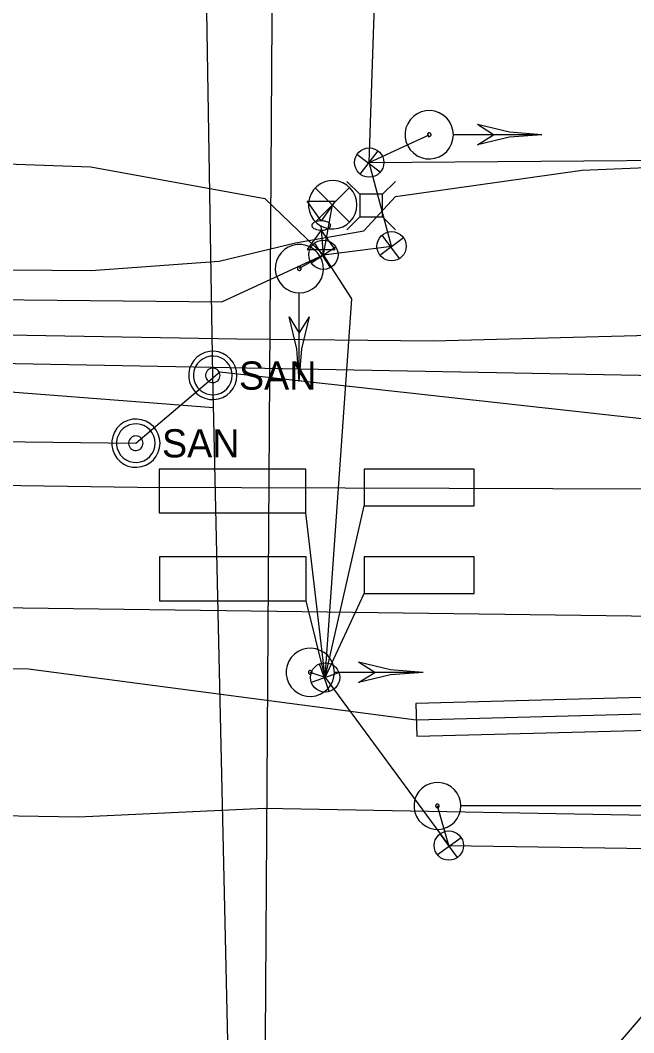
# Model space of a CAD drawing. Extents: x 600849 to 606371, y 330010 to 403088.
# Drawn here: x 604965.8 to 605049.6, y 332631.5 to 332769.8 of the extents above; entities that cross this region are included whole.
import ezdxf

# ---------------------------------------------------------------- set-up
doc = ezdxf.new("R2010")
doc.units = 0
for name, color, linetype in [('E_LTG_CID', 7, 'Continuous'), ('E_SIG', 7, 'Continuous'), ('E_SIG_Conduit', 7, 'Continuous'), ('E_UTL_AG', 7, 'Continuous'), ('E_UTL_AG_Bold', 7, 'Continuous'), ('E_UTL_E_UG', 7, 'Continuous'), ('E_UTL_G_UG', 7, 'Continuous'), ('E_UTL_Loop_UG', 7, 'Continuous'), ('E_UTL_SAN', 7, 'Continuous'), ('E_UTL_SAN_UG', 7, 'Continuous'), ('E_UTL_SAN_UG_MMSD', 7, 'Continuous'), ('E_UTL_T_UG', 7, 'Continuous'), ('E_UTL_TV_UG', 7, 'Continuous'), ('E_UTL_W_UG', 7, 'Continuous')]:
    doc.layers.add(name, color=color, linetype=linetype)

# ---------------------------------------------------------------- blocks, each defined once
blk = doc.blocks.new('_U300')
at = {"layer": 'E_SIG'}
for p, q in [((0, 6.1), (0, -6.1)), ((-6.09, 0.4), (6.1, 0.4))]:
    blk.add_line(p, q, dxfattribs=at)
blk.add_circle((0, 0.01), 6.1, dxfattribs=at)
blk = doc.blocks.new('_U305')
at = {"layer": 'E_SIG'}
for p, q in [((0, 6.1), (0, -6.1)), ((-6.09, 0.4), (6.1, 0.4))]:
    blk.add_line(p, q, dxfattribs=at)
blk.add_circle((0, 0.01), 6.1, dxfattribs=at)
blk = doc.blocks.new('_U306')
at = {"layer": 'E_SIG'}
for p, q in [((0, 6.1), (0, -6.1)), ((-6.09, 0.4), (6.1, 0.4))]:
    blk.add_line(p, q, dxfattribs=at)
blk.add_circle((0, 0.01), 6.1, dxfattribs=at)
blk = doc.blocks.new('_U307')
at = {"layer": 'E_SIG'}
for p, q in [((0, 6.1), (0, -6.1)), ((-6.09, 0.4), (6.1, 0.4))]:
    blk.add_line(p, q, dxfattribs=at)
blk.add_circle((0, 0.01), 6.1, dxfattribs=at)
blk = doc.blocks.new('_U308')
at = {"layer": 'E_SIG'}
for p, q in [((0, 6.1), (0, -6.1)), ((-6.09, 0.4), (6.1, 0.4))]:
    blk.add_line(p, q, dxfattribs=at)
blk.add_circle((0, 0.01), 6.1, dxfattribs=at)

msp = doc.modelspace()

# ---------------------------------------------------------------- linework, layer by layer
at = {"layer": 'E_LTG_CID'}
msp.add_lwpolyline([(604931.85, 331581.07), (604937.27, 331603.67), (604947.8, 331650.94), (604952, 331678.28), (604955.83, 331701.76), (604989.48, 331966.47), (604996.27, 332242.26), (604998.49, 332512.59), (605000.29, 332783.81), (605002.15, 332931.75), (605000.64, 332964.83), (605000.69, 332966.2), (605002.17, 333011.44), (605003.78, 333073.37), (605005.15, 333128.46), (605004.43, 333142.5)], dxfattribs=at)
at = {"layer": 'E_SIG'}
for points in [[(605024.93, 332754.16), (605024.87, 332754.79), (605024.69, 332755.39), (605024.41, 332755.95), (605024.02, 332756.44), (605023.54, 332756.85), (605023, 332757.16), (605022.41, 332757.37), (605021.79, 332757.46), (605021.16, 332757.43), (605020.55, 332757.28), (605019.98, 332757.02), (605019.47, 332756.65), (605019.04, 332756.2), (605018.7, 332755.67), (605018.46, 332755.09), (605018.35, 332754.47), (605018.35, 332753.85), (605018.46, 332753.23), (605018.7, 332752.65), (605019.04, 332752.12), (605019.47, 332751.67), (605019.98, 332751.3), (605020.55, 332751.04), (605021.16, 332750.89), (605021.79, 332750.86), (605022.41, 332750.95), (605023, 332751.16), (605023.54, 332751.47), (605024.02, 332751.88), (605024.41, 332752.38), (605024.69, 332752.93), (605024.87, 332753.54), (605024.93, 332754.16)], [(605037.03, 332754.16), (605032.58, 332754.51), (605028.23, 332755.54)], [(605030.43, 332754.16), (605028.23, 332755.54)], [(605021.88, 332754.16), (605021.88, 332754.21), (605021.87, 332754.25), (605021.84, 332754.3), (605021.81, 332754.34), (605021.78, 332754.37), (605021.74, 332754.39), (605021.69, 332754.41), (605021.64, 332754.41), (605021.59, 332754.41), (605021.55, 332754.4), (605021.5, 332754.38), (605021.47, 332754.35), (605021.43, 332754.32), (605021.41, 332754.28), (605021.39, 332754.23), (605021.38, 332754.18), (605021.38, 332754.14), (605021.39, 332754.09), (605021.41, 332754.05), (605021.43, 332754), (605021.47, 332753.97), (605021.5, 332753.94), (605021.55, 332753.92), (605021.59, 332753.91), (605021.64, 332753.91), (605021.69, 332753.92), (605021.74, 332753.93), (605021.78, 332753.96), (605021.81, 332753.99), (605021.84, 332754.02), (605021.87, 332754.07), (605021.88, 332754.11), (605021.88, 332754.16)], [(605037.03, 332754.16), (605024.99, 332754.16)], [(605037.03, 332754.16), (605032.58, 332753.82), (605028.23, 332752.79)], [(605028.23, 332752.79), (605030.43, 332754.16)], [(605011.75, 332744.6), (605011.7, 332745.22), (605011.52, 332745.82), (605011.23, 332746.38), (605010.84, 332746.87), (605010.37, 332747.28), (605009.83, 332747.6), (605009.23, 332747.8), (605008.61, 332747.89), (605007.99, 332747.86), (605007.38, 332747.72), (605006.8, 332747.45), (605006.29, 332747.09), (605005.86, 332746.64), (605005.52, 332746.11), (605005.29, 332745.53), (605005.17, 332744.91), (605005.17, 332744.28), (605005.29, 332743.67), (605005.52, 332743.08), (605005.86, 332742.56), (605006.29, 332742.1), (605006.8, 332741.74), (605007.38, 332741.48), (605007.99, 332741.33), (605008.61, 332741.3), (605009.23, 332741.39), (605009.83, 332741.59), (605010.37, 332741.91), (605010.84, 332742.32), (605011.23, 332742.81), (605011.52, 332743.37), (605011.7, 332743.97), (605011.75, 332744.6)], [(605010.72, 332746.93), (605006.11, 332742.27)], [(605006.11, 332746.88), (605010.76, 332742.23)], [(605003.9, 332732.58), (605004.53, 332732.64), (605005.13, 332732.82), (605005.69, 332733.1), (605006.18, 332733.49), (605006.59, 332733.97), (605006.91, 332734.51), (605007.11, 332735.1), (605007.2, 332735.72), (605007.17, 332736.35), (605007.02, 332736.96), (605006.76, 332737.53), (605006.4, 332738.04), (605005.94, 332738.47), (605005.42, 332738.81), (605004.83, 332739.05), (605004.22, 332739.17), (605003.59, 332739.17), (605002.97, 332739.05), (605002.39, 332738.81), (605001.86, 332738.47), (605001.41, 332738.04), (605001.05, 332737.53), (605000.78, 332736.96), (605000.64, 332736.35), (605000.61, 332735.72), (605000.7, 332735.1), (605000.9, 332734.51), (605001.22, 332733.97), (605001.63, 332733.49), (605002.12, 332733.1), (605002.68, 332732.82), (605003.28, 332732.64), (605003.9, 332732.58)], [(605003.9, 332735.63), (605003.95, 332735.63), (605004, 332735.65), (605004.04, 332735.67), (605004.08, 332735.7), (605004.11, 332735.73), (605004.13, 332735.78), (605004.15, 332735.82), (605004.16, 332735.87), (605004.15, 332735.92), (605004.14, 332735.96), (605004.12, 332736.01), (605004.09, 332736.05), (605004.06, 332736.08), (605004.02, 332736.11), (605003.97, 332736.12), (605003.93, 332736.13), (605003.88, 332736.13), (605003.83, 332736.12), (605003.79, 332736.11), (605003.75, 332736.08), (605003.71, 332736.05), (605003.68, 332736.01), (605003.66, 332735.96), (605003.65, 332735.92), (605003.65, 332735.87), (605003.66, 332735.82), (605003.67, 332735.78), (605003.7, 332735.73), (605003.73, 332735.7), (605003.77, 332735.67), (605003.81, 332735.65), (605003.86, 332735.63), (605003.9, 332735.63)], [(605003.9, 332720.48), (605003.9, 332732.52)], [(605003.9, 332720.48), (605003.56, 332724.93), (605002.53, 332729.28)], [(605002.53, 332729.28), (605003.9, 332727.08)], [(605003.9, 332720.48), (605004.25, 332724.93), (605005.28, 332729.28)], [(605003.9, 332727.08), (605005.28, 332729.28)], [(605008.69, 332680.75), (605008.63, 332681.38), (605008.46, 332681.98), (605008.17, 332682.54), (605007.78, 332683.03), (605007.31, 332683.44), (605006.76, 332683.75), (605006.17, 332683.96), (605005.55, 332684.05), (605004.92, 332684.02), (605004.31, 332683.87), (605003.74, 332683.61), (605003.23, 332683.25), (605002.8, 332682.79), (605002.46, 332682.27), (605002.23, 332681.68), (605002.11, 332681.07), (605002.11, 332680.44), (605002.23, 332679.82), (605002.46, 332679.24), (605002.8, 332678.71), (605003.23, 332678.26), (605003.74, 332677.9), (605004.31, 332677.63), (605004.92, 332677.49), (605005.55, 332677.46), (605006.17, 332677.55), (605006.76, 332677.75), (605007.31, 332678.07), (605007.78, 332678.48), (605008.17, 332678.97), (605008.46, 332679.53), (605008.63, 332680.13), (605008.69, 332680.75)], [(605020.79, 332680.75), (605016.34, 332681.1), (605011.99, 332682.13)], [(605014.19, 332680.75), (605011.99, 332682.13)], [(605005.65, 332680.75), (605005.64, 332680.8), (605005.63, 332680.85), (605005.61, 332680.89), (605005.58, 332680.93), (605005.54, 332680.96), (605005.5, 332680.98), (605005.45, 332681), (605005.41, 332681.01), (605005.36, 332681), (605005.31, 332680.99), (605005.27, 332680.97), (605005.23, 332680.94), (605005.2, 332680.91), (605005.17, 332680.87), (605005.15, 332680.82), (605005.14, 332680.78), (605005.14, 332680.73), (605005.15, 332680.68), (605005.17, 332680.64), (605005.2, 332680.6), (605005.23, 332680.56), (605005.27, 332680.53), (605005.31, 332680.51), (605005.36, 332680.5), (605005.41, 332680.5), (605005.45, 332680.51), (605005.5, 332680.52), (605005.54, 332680.55), (605005.58, 332680.58), (605005.61, 332680.62), (605005.63, 332680.66), (605005.64, 332680.71), (605005.65, 332680.75)], [(605007.43, 332680.06), (605005.39, 332680.75)], [(605020.79, 332680.75), (605008.75, 332680.75)], [(605020.79, 332680.75), (605016.34, 332680.41), (605011.99, 332679.38)], [(605011.99, 332679.38), (605014.19, 332680.75)], [(605025.96, 332662.51), (605025.9, 332663.12), (605025.73, 332663.7), (605025.45, 332664.25), (605025.08, 332664.72), (605024.62, 332665.12), (605024.09, 332665.43), (605023.51, 332665.63), (605022.91, 332665.71), (605022.3, 332665.68), (605021.71, 332665.54), (605021.16, 332665.29), (605020.66, 332664.93), (605020.24, 332664.49), (605019.91, 332663.98), (605019.69, 332663.42), (605019.57, 332662.82), (605019.57, 332662.21), (605019.69, 332661.61), (605019.91, 332661.05), (605020.24, 332660.53), (605020.66, 332660.09), (605021.16, 332659.74), (605021.71, 332659.49), (605022.3, 332659.34), (605022.91, 332659.31), (605023.51, 332659.4), (605024.09, 332659.6), (605024.62, 332659.91), (605025.08, 332660.3), (605025.45, 332660.78), (605025.73, 332661.32), (605025.9, 332661.91), (605025.96, 332662.51)], [(605023, 332662.51), (605023, 332662.56), (605022.99, 332662.61), (605022.96, 332662.65), (605022.94, 332662.68), (605022.9, 332662.71), (605022.86, 332662.74), (605022.82, 332662.75), (605022.77, 332662.76), (605022.72, 332662.76), (605022.68, 332662.75), (605022.64, 332662.73), (605022.6, 332662.7), (605022.57, 332662.67), (605022.54, 332662.63), (605022.52, 332662.58), (605022.51, 332662.54), (605022.51, 332662.49), (605022.52, 332662.45), (605022.54, 332662.4), (605022.57, 332662.36), (605022.6, 332662.33), (605022.64, 332662.3), (605022.68, 332662.28), (605022.72, 332662.27), (605022.77, 332662.27), (605022.82, 332662.28), (605022.86, 332662.29), (605022.9, 332662.31), (605022.94, 332662.35), (605022.96, 332662.38), (605022.99, 332662.42), (605023, 332662.47), (605023, 332662.51)], [(605024.31, 332657.1), (605022.76, 332662.51)], [(605052.65, 332662.52), (605026.01, 332662.52)], [(605045.18, 332662.52), (605045.18, 332662.52)]]:
    msp.add_lwpolyline(points, dxfattribs=at)
at = {"layer": 'E_SIG_Conduit'}
msp.add_line((605007.19, 332737.78), (605003.9, 332735.88), dxfattribs=at)
for points in [[(605013.44, 332750.37), (605018.8, 332909.2), (605014.77, 333003.78)], [(605013.44, 332750.37), (605021.63, 332754.16)], [(605007.43, 332680.06), (605011.08, 332731.74), (605007.19, 332737.78), (605016.5, 332738.93), (605013.44, 332750.37), (605060.3, 332750.72), (605093.78, 332739.36)], [(605007.19, 332737.78), (605008.45, 332744.6)], [(605007.19, 332737.78), (605006.89, 332741.77)], [(604921.39, 332732.09), (604993.31, 332731.34), (605007.19, 332737.78)], [(605007.43, 332680.06), (605024.31, 332657.1), (605054.73, 332656.67), (605096.42, 332660.59), (605109.2, 332679.54), (605110.22, 332731.89)]]:
    msp.add_lwpolyline(points, dxfattribs=at)
at = {"layer": 'E_UTL_AG'}
for points in [[(605004.99, 332745.07), (605008.8, 332745.07)], [(605006.89, 332742.4), (605004.99, 332745.07)], [(605008.8, 332745.07), (605006.89, 332742.4)], [(605008.16, 332741.77), (605008.14, 332741.89), (605008.07, 332742), (605007.96, 332742.11), (605007.81, 332742.21), (605007.63, 332742.28), (605007.42, 332742.35), (605007.19, 332742.38), (605006.95, 332742.4), (605006.71, 332742.4), (605006.48, 332742.37), (605006.26, 332742.32), (605006.06, 332742.25), (605005.89, 332742.16), (605005.76, 332742.06), (605005.67, 332741.95), (605005.63, 332741.83), (605005.63, 332741.71), (605005.67, 332741.59), (605005.76, 332741.48), (605005.89, 332741.37), (605006.06, 332741.29), (605006.26, 332741.22), (605006.48, 332741.17), (605006.71, 332741.14), (605006.95, 332741.13), (605007.19, 332741.15), (605007.42, 332741.19), (605007.63, 332741.25), (605007.81, 332741.33), (605007.96, 332741.42), (605008.07, 332741.53), (605008.14, 332741.65), (605008.16, 332741.77)], [(605006.89, 332741.13), (605004.99, 332738.47)], [(605008.8, 332738.47), (605006.89, 332741.13)], [(605004.99, 332738.47), (605008.8, 332738.47)]]:
    msp.add_lwpolyline(points, dxfattribs=at)
at = {"layer": 'E_UTL_AG_Bold'}
for points in [[(605012.16, 332746.04), (605010.41, 332747.79)], [(605015.26, 332746.04), (605017.01, 332747.79)], [(605015.26, 332746.04), (605012.16, 332746.04)], [(605012.16, 332746.04), (605012.16, 332742.94)], [(605015.26, 332742.94), (605015.26, 332746.04)], [(605012.16, 332742.94), (605010.41, 332741.19)], [(605012.16, 332742.94), (605015.26, 332742.94)], [(605015.26, 332742.94), (605017.01, 332741.19)]]:
    msp.add_lwpolyline(points, dxfattribs=at)
at = {"layer": 'E_UTL_E_UG'}
msp.add_line((604415.87, 332733.34), (605162.93, 332719.18), dxfattribs=at)
msp.add_lwpolyline([(604883.85, 332749.45), (604890.54, 332751.38), (604904.52, 332751.83), (604930.8, 332751.36), (604975.43, 332749.76), (604999.19, 332745.44), (605007.19, 332737.78)], dxfattribs=at)
at = {"layer": 'E_UTL_G_UG'}
msp.add_line((604453.34, 332696.36), (605095.21, 332687.86), dxfattribs=at)
msp.add_line((604453.34, 332696.36), (605095.21, 332687.86), dxfattribs=at)
msp.add_lwpolyline([(605000.09, 332338.31), (605000.11, 332381.53), (605000.58, 332421.33), (605000.12, 332494.14), (605001.25, 332517.82), (605001.72, 332543.05), (605001.99, 332582.9), (605009.14, 332588.51), (605017.08, 332595.02), (605025.17, 332603.98), (605053.2, 332636.73), (605068.82, 332651.42), (605069.91, 332651.64), (605092.37, 332651), (605098.99, 332656), (605103.96, 332660.87), (605106.76, 332663.11), (605116.6, 332673.18), (605136.39, 332673.6), (605163.97, 332673.14), (605215.25, 332672.77), (605447.16, 332669.14)], dxfattribs=at)
at = {"layer": 'E_UTL_Loop_UG'}
for p, q in [((605004.77, 332708.51), (604984.77, 332708.51)), ((604984.77, 332708.51), (604984.77, 332702.51)), ((605004.77, 332702.51), (605004.77, 332708.51)), ((604984.77, 332702.51), (605004.77, 332702.51)), ((605007.43, 332680.06), (605004.77, 332702.51)), ((605007.43, 332680.06), (605012.77, 332703.51)), ((605004.82, 332696.51), (604984.82, 332696.51)), ((604984.82, 332696.51), (604984.82, 332690.51)), ((605004.82, 332690.51), (605004.82, 332696.51)), ((605007.43, 332680.06), (605012.77, 332691.51)), ((604984.82, 332690.51), (605004.82, 332690.51)), ((605007.43, 332680.06), (605004.82, 332690.51))]:
    msp.add_line(p, q, dxfattribs=at)
for points in [[(605027.77, 332703.51), (605027.77, 332708.51), (605012.77, 332708.51), (605012.77, 332703.51), (605027.77, 332703.51)], [(605027.77, 332691.51), (605027.77, 332696.51), (605012.77, 332696.51), (605012.77, 332691.51), (605027.77, 332691.51)]]:
    msp.add_lwpolyline(points, dxfattribs=at)
at = {"layer": 'E_UTL_SAN'}
for points in [[(604995.39, 332721.3), (604995.34, 332721.92), (604995.16, 332722.52), (604994.87, 332723.08), (604994.48, 332723.57), (604994.01, 332723.98), (604993.47, 332724.3), (604992.87, 332724.5), (604992.25, 332724.59), (604991.63, 332724.56), (604991.02, 332724.41), (604990.44, 332724.15), (604989.93, 332723.79), (604989.5, 332723.34), (604989.16, 332722.81), (604988.93, 332722.23), (604988.81, 332721.61), (604988.81, 332720.98), (604988.93, 332720.37), (604989.16, 332719.78), (604989.5, 332719.26), (604989.93, 332718.8), (604990.44, 332718.44), (604991.02, 332718.18), (604991.63, 332718.03), (604992.25, 332718), (604992.87, 332718.09), (604993.47, 332718.29), (604994.01, 332718.61), (604994.48, 332719.02), (604994.87, 332719.51), (604995.16, 332720.07), (604995.34, 332720.67), (604995.39, 332721.3)], [(604994.73, 332721.3), (604994.69, 332721.8), (604994.55, 332722.28), (604994.32, 332722.72), (604994.01, 332723.12), (604993.63, 332723.45), (604993.19, 332723.7), (604992.72, 332723.86), (604992.22, 332723.93), (604991.72, 332723.91), (604991.23, 332723.79), (604990.77, 332723.58), (604990.37, 332723.29), (604990.02, 332722.93), (604989.75, 332722.51), (604989.56, 332722.04), (604989.47, 332721.55), (604989.47, 332721.04), (604989.56, 332720.55), (604989.75, 332720.09), (604990.02, 332719.66), (604990.37, 332719.3), (604990.77, 332719.01), (604991.23, 332718.8), (604991.72, 332718.68), (604992.22, 332718.66), (604992.72, 332718.73), (604993.19, 332718.89), (604993.63, 332719.15), (604994.01, 332719.47), (604994.32, 332719.87), (604994.55, 332720.31), (604994.69, 332720.8), (604994.73, 332721.3)], [(604993.08, 332721.3), (604993.07, 332721.48), (604993.01, 332721.66), (604992.93, 332721.83), (604992.81, 332721.98), (604992.67, 332722.1), (604992.51, 332722.2), (604992.33, 332722.26), (604992.14, 332722.28), (604991.95, 332722.28), (604991.77, 332722.23), (604991.6, 332722.15), (604991.45, 332722.04), (604991.32, 332721.91), (604991.21, 332721.75), (604991.14, 332721.57), (604991.11, 332721.39), (604991.11, 332721.2), (604991.14, 332721.02), (604991.21, 332720.84), (604991.32, 332720.68), (604991.45, 332720.55), (604991.6, 332720.44), (604991.77, 332720.36), (604991.95, 332720.32), (604992.14, 332720.31), (604992.33, 332720.33), (604992.51, 332720.4), (604992.67, 332720.49), (604992.81, 332720.61), (604992.93, 332720.76), (604993.01, 332720.93), (604993.07, 332721.11), (604993.08, 332721.3)], [(604984.89, 332712.04), (604984.83, 332712.67), (604984.65, 332713.27), (604984.36, 332713.83), (604983.98, 332714.32), (604983.5, 332714.73), (604982.96, 332715.04), (604982.37, 332715.25), (604981.74, 332715.34), (604981.12, 332715.31), (604980.51, 332715.16), (604979.94, 332714.9), (604979.43, 332714.54), (604978.99, 332714.08), (604978.65, 332713.55), (604978.42, 332712.97), (604978.3, 332712.36), (604978.3, 332711.73), (604978.42, 332711.11), (604978.65, 332710.53), (604978.99, 332710), (604979.43, 332709.55), (604979.94, 332709.18), (604980.51, 332708.92), (604981.12, 332708.78), (604981.74, 332708.75), (604982.37, 332708.84), (604982.96, 332709.04), (604983.5, 332709.35), (604983.98, 332709.77), (604984.36, 332710.26), (604984.65, 332710.82), (604984.83, 332711.42), (604984.89, 332712.04)], [(604984.23, 332712.04), (604984.18, 332712.54), (604984.04, 332713.02), (604983.81, 332713.47), (604983.5, 332713.86), (604983.12, 332714.19), (604982.68, 332714.44), (604982.21, 332714.61), (604981.71, 332714.68), (604981.21, 332714.66), (604980.72, 332714.54), (604980.27, 332714.33), (604979.86, 332714.04), (604979.51, 332713.67), (604979.24, 332713.25), (604979.05, 332712.79), (604978.96, 332712.29), (604978.96, 332711.79), (604979.05, 332711.3), (604979.24, 332710.83), (604979.51, 332710.41), (604979.86, 332710.05), (604980.27, 332709.76), (604980.72, 332709.55), (604981.21, 332709.43), (604981.71, 332709.41), (604982.21, 332709.48), (604982.68, 332709.64), (604983.12, 332709.89), (604983.5, 332710.22), (604983.81, 332710.62), (604984.04, 332711.06), (604984.18, 332711.54), (604984.23, 332712.04)], [(604982.58, 332712.04), (604982.56, 332712.23), (604982.51, 332712.41), (604982.42, 332712.58), (604982.3, 332712.73), (604982.16, 332712.85), (604982, 332712.94), (604981.82, 332713), (604981.63, 332713.03), (604981.45, 332713.02), (604981.26, 332712.98), (604981.09, 332712.9), (604980.94, 332712.79), (604980.81, 332712.65), (604980.71, 332712.5), (604980.64, 332712.32), (604980.6, 332712.14), (604980.6, 332711.95), (604980.64, 332711.76), (604980.71, 332711.59), (604980.81, 332711.43), (604980.94, 332711.29), (604981.09, 332711.19), (604981.26, 332711.11), (604981.45, 332711.06), (604981.63, 332711.05), (604981.82, 332711.08), (604982, 332711.14), (604982.16, 332711.24), (604982.3, 332711.36), (604982.42, 332711.51), (604982.51, 332711.67), (604982.56, 332711.86), (604982.58, 332712.04)]]:
    msp.add_lwpolyline(points, dxfattribs=at)
at = {"layer": 'E_UTL_SAN_UG'}
for p, q in [((604981.59, 332712.04), (604993.06, 332721.79)), ((604993.06, 332721.79), (605095.5, 332710.46)), ((604737.44, 332715.28), (604981.59, 332712.04))]:
    msp.add_line(p, q, dxfattribs=at)
msp.add_lwpolyline([(604878.95, 332725.67), (604992.19, 332716.93), (604992.09, 332721.29)], dxfattribs=at)
at = {"layer": 'E_UTL_SAN_UG_MMSD'}
msp.add_line((605001.66, 332297.25), (604992.09, 332721.29), dxfattribs=at)
msp.add_lwpolyline([(604992.09, 332721.29), (604983.2, 333259.95), (604978.83, 333311.92)], dxfattribs=at)
at = {"layer": 'E_UTL_T_UG'}
for p, q in [((604356.98, 332714.56), (604981.82, 332706.04)), ((604981.82, 332706.04), (605422.08, 332704.55))]:
    msp.add_line(p, q, dxfattribs=at)
at = {"layer": 'E_UTL_TV_UG'}
for points in [[(604667.79, 332752.28), (604716.52, 332751.29), (604772.47, 332750.78), (604802.28, 332745.13), (604821.11, 332741.83), (604839.24, 332737.01), (604851.39, 332734.26), (604870.7, 332730.27), (604882.93, 332728.13), (604900.25, 332727.49), (604950.98, 332727.08), (604995.39, 332726.29), (605022.19, 332726.03), (605060.41, 332727.04), (605084.56, 332725.74), (605114.2, 332728.34), (605148.01, 332733.35)], [(604916.23, 332736.12), (604975.49, 332735.63), (604992.97, 332736.89), (605003.39, 332739.42), (605012.69, 332741.02), (605017.03, 332745.71), (605042.52, 332749.33), (605064.38, 332750.23), (605090.09, 332749.99), (605094.48, 332746.45), (605107.38, 332741), (605124.95, 332737.5), (605134.08, 332736.35), (605152.24, 332733.9)]]:
    msp.add_lwpolyline(points, dxfattribs=at)
at = {"layer": 'E_UTL_W_UG'}
for p, q in [((604900.94, 332682.11), (604966.93, 332681.23)), ((604966.93, 332681.23), (605019.87, 332674.26)), ((605019.87, 332674.26), (605230.04, 332679.7))]:
    msp.add_line(p, q, dxfattribs=at)
msp.add_lwpolyline([(605019.93, 332672.02), (605079.91, 332673.57), (605079.79, 332678.07), (605019.81, 332676.51)], close=True, dxfattribs=at)
for points in [[(604777.25, 332665.16), (604781.5, 332664.88), (604910.94, 332662.05), (604973.76, 332661.03), (604999.15, 332662.21)], [(604999.15, 332662.21), (605058.91, 332661.12), (605080.34, 332636.95)]]:
    msp.add_lwpolyline(points, dxfattribs=at)

# ---------------------------------------------------------------- block references
at = {"layer": 'E_SIG'}
for name, p, xscale, yscale, rotation in [('_U308', (605013.44, 332750.37), 0.32808333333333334, 0.3280833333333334, 142.82457380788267), ('_U307', (605016.5, 332738.93), 0.32808333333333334, 0.3280833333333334, 126.66560630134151), ('_U306', (605007.19, 332737.78), 0.32808333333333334, 0.32808333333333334, 123.07960455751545), ('_U305', (605007.43, 332680.06), 0.3280833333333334, 0.32808333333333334, 109.3471628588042), ('_U300', (605024.31, 332657.1), 0.3280833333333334, 0.32808333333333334, -144.15690978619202)]:
    msp.add_blockref(name, p, dxfattribs=dict(at, xscale=xscale, yscale=yscale, rotation=rotation))

# ---------------------------------------------------------------- texts
at = {"layer": 'E_UTL_SAN'}
for p in [(604995.66, 332719.35), (604985.15, 332710.1)]:
    msp.add_text('SAN', height=3.849, dxfattribs=at).set_placement(p)

doc.saveas('drawing.dxf')
